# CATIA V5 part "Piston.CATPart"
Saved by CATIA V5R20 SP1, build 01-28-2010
Part number: Piston
Bounding box of the stored display mesh (mm): x -46 to 46, y -45.932 to 45.932, z 0 to 70.683
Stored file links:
  D:\v5_r20\psrt_files_downloaded\c13-catia-v5r20-prt\c13-catia-v5r20-figr-13-41\Part & Asm files\Piston.CATPart
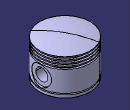
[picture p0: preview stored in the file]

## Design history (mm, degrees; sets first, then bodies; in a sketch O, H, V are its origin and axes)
Body1 (main body)
  Sketch1 on yz-plane, origin (0, 0, 0), H (0, 1, 0), V (0, 0, 1)
    line L1 (37, 0) -> (46, 0)
    line L2 (46, 0) -> (46, 5)
    construction line L3 (0, 62) -> (0, 0)
    point P2 (46, 65)
    line L4 (42.5, 45) -> (42.5, 48)
    point P5 (46, 48)
    point P6 (46, 50)
    point P7 (46, 53)
    point P8 (46, 55)
    point P9 (46, 58)
    point P10 (46, 60)
    line L5 (42.5, 48) -> (46, 48)
    line L6 (42.5, 45) -> (46, 45)
    line L7 (42.5, 50) -> (46, 50)
    point P13 (42.5, 50)
    line L8 (42.5, 53) -> (46, 53)
    point P14 (42.5, 53)
    line L9 (42.5, 55) -> (46, 55)
    point P15 (42.5, 55)
    line L10 (42.5, 58) -> (46, 58)
    point P16 (42.5, 58)
    line L11 (42.5, 60) -> (46, 60)
    point P17 (42.5, 60)
    line L12 (46, 48) -> (46, 50)
    line L13 (46, 53) -> (46, 55)
    line L14 (46, 58) -> (46, 60)
    line L15 (42.5, 50) -> (42.5, 53)
    line L16 (42.5, 55) -> (42.5, 58)
    line L17 (42.5, 60) -> (42.5, 63)
    line L18 (42.5, 63) -> (46, 63)
    point P18 (46, 63)
    line L19 (46, 63) -> (46, 65)
    line L20 (46, 5) -> (42.5, 5)
    point P20 (42.5, 5)
    line L21 (42.5, 5) -> (42.5, 7)
    line L22 (42.5, 7) -> (46, 7)
    point P22 (46, 7)
    line L23 (46, 7) -> (46, 45)
    point P23 (-46, 65)
    point P24 (-46, 63)
    construction line L24 (-46, 63) -> (-46, 65)
    arc A1 centre (0, -118.3167) radius 189 from (46, 65) to (0, 70.6833) ccw
    point P26 (0, 55)
    line L25 (37, 0) -> (37, 62)
    line L26 (37, 62) -> (0, 62)
    line L27 (0, 62) -> (0, 70.6833)
    construction arc A2 centre (0, -118.3167) radius 189 from (0, 70.6833) to (-46, 65) ccw
    distance L2 L4 = 3.5
    distance L6 L1 = 45
    length L4 = 3
    length L15 = 3
    length L16 = 3
    length L13 = 2
    length L12 = 2
    length L17 = 3
    length L19 = 2
    length L14 = 2
    length L21 = 2
    distance L1 L22 = 7
    radius A1 = 189
    length L26 = 37
    length L25 = 62
    distance L2 L3 = 46
    horizontal: L1 H, L5 H, L6 H, L7 H, L8 H, L9 H, L10 H, L11 H, L18 H, L20 H, L22 H, L26 H
    vertical: L2 V, L3 V, L12 V, L13 V, L14 V, L19 V, L21 V, L23 V, L25 V, L27 V, L17 V, L16 V, L15 V, L4 V
    coincidence: L2 P5, L2 P6, L2 P7, L2 P8, L2 P9, L2 P10, L4 P13, L4 P14, L4 P15, L4 P16, L4 P17, L2 L12, L12 L13, L13 L14, L4 L15, L15 L16, L16 L17, P18 L14, L14 L19, P20 L15, P22 L2, L2 L23, P26 L3, P26 L9, L1 H, A1 A2
    symmetry: P2 P23 L3, P18 P24 L3, L19 L24 L3
  Shaft1: profile Sketch1, axis Sketch1.V, angle 360
  Sketch2 on yz-plane, origin (0, 0, 0), H (0, 1, 0), V (0, 0, 1)
    circle A1 centre (0, 26) radius 19.5
    point P1 (0, 26)
    radius A1 = 19.5
    distance H P1 = 26
    coincidence: P1 V
  Pad1: profile Sketch2, direction (1, 0, 0), up to the existing solid (limit type 2), opposite side length -25
  Mirror1: of Pad1, Sketch2, about yz-plane
  Sketch3 on yz-plane, origin (0, 0, 0), H (0, 1, 0), V (0, 0, 1)
    circle A1 centre (0, 26) radius 18
    point P1 (0, 26)
    reference projected circle E1 centre (0, 26) radius 19.5 from edge of Pad1
    radius A1 = 18
    coincidence: P1 V
    concentricity: A1 E1
  Pocket1: profile Sketch3, direction (-1, 0, 0), length 42.5, opposite side length -50
  Mirror2: of Pocket1, Sketch3, about yz-plane
  Sketch4 on yz-plane, origin (0, 0, 0), H (0, 1, 0), V (0, 0, 1)
    circle A1 centre (0, 26) radius 11
    point P1 (0, 26)
    reference projected circle E1 centre (0, 26) radius 19.5 from edge of Pad1
    radius A1 = 11
    coincidence: P1 V
    concentricity: A1 E1
  Pocket2: profile Sketch4, direction (-1, 0, 0), length 50.5, mirrored extent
